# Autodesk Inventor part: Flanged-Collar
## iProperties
Shininess: 64.0
Length Units: 11269
Angle Units: 11279
Time Units: 11290
Mass Units: 11283
Length Display Precision: 3
Angle Display Precision: 2
Compacted: True
Part Number: Flanged-Collar
Document SubType Name: Modeling
Created: 2004-01
Designer: Administrator
Manufacturer: Standard
Standards Organization: Custom
Density: 1 g/cm^3
Density: 0.0
Volumn: 0.0
Area: 0.0
PropertySet Name: Model Information
Control State: 0
Master: False
Checked Out: False
Author: Administrator
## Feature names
1. Extrusion1
2. Extrusion2
3. Fillet1
4. Hole1
5. Revolution1
6. Extrusion3
7. Extrusion4
8. Hole2
9. Mirror1
10. Hole3
11. Circular Pattern1
12. Chamfer1
13. Chamfer2
14. Fillet2
15. Fillet3
16. Fillet4
17. Fillet5
